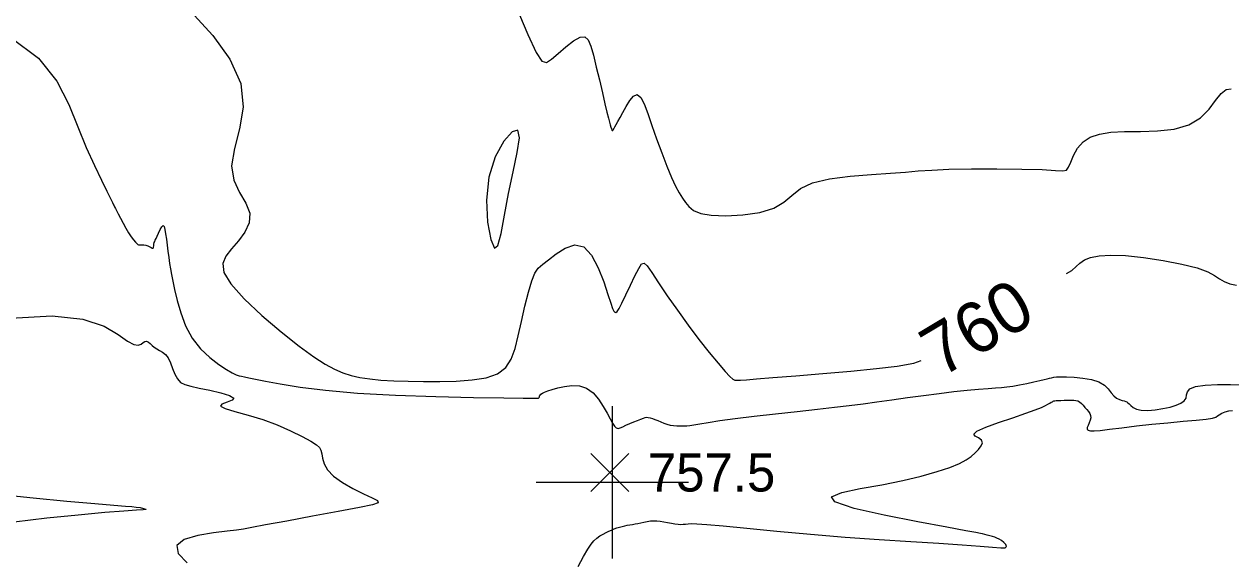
# Model space of a CAD drawing. Extents: x 2566142 to 2571431, y 418755 to 421584.
# Drawn here: x 2567768.3 to 2568243.6, y 420968.6 to 421180.6 of the extents above; entities that cross this region are included whole.
import ezdxf

# ---------------------------------------------------------------- set-up
doc = ezdxf.new("R2010")
doc.units = 0
for name, color, linetype in [('Contour_ADS_Label_Major', 7, 'Continuous'), ('Contour_ADS_Major', 7, 'Continuous'), ('Contour_ADS_Minor', 7, 'Continuous'), ('Contour_ADS_Spot_Elevation', 7, 'Continuous'), ('Contour_ADS_Tick', 7, 'Continuous')]:
    doc.layers.add(name, color=color, linetype=linetype)

# ---------------------------------------------------------------- blocks, each defined once
blk = doc.blocks.new('S890')
at = {"layer": 'Contour_ADS_Tick'}
for p, q in [((0, -0.5), (0, 0.5)), ((-0.5, 0), (0.5, 0))]:
    blk.add_line(p, q, dxfattribs=at)
blk = doc.blocks.new('S750')
at = {"layer": 'Contour_ADS_Spot_Elevation'}
for p, q in [((-0.5, 0.498), (0.5, -0.498)), ((-0.498, -0.5), (0.498, 0.5))]:
    blk.add_line(p, q, dxfattribs=at)

msp = doc.modelspace()

# ---------------------------------------------------------------- linework, layer by layer
at = {"layer": 'Contour_ADS_Major'}
for points in [[(2567835.26, 421184.06), (2567842.63, 421176.02), (2567849.28, 421166.75), (2567853.61, 421157.11), (2567854.55, 421147.85), (2567853.18, 421139.26), (2567851.12, 421131.49), (2567849.96, 421124.71), (2567850.86, 421119.02), (2567853.13, 421114.2), (2567855.61, 421109.97), (2567857.17, 421106.07), (2567856.94, 421102.28), (2567855.25, 421098.62), (2567852.75, 421095.17), (2567850.05, 421092.02), (2567847.79, 421089.16), (2567846.57, 421086.21), (2567847, 421082.7), (2567849.7, 421078.16), (2567854.97, 421072.33), (2567861.97, 421065.78), (2567869.6, 421059.29), (2567876.7, 421053.65), (2567882.42, 421049.44), (2567886.91, 421046.52), (2567890.59, 421044.54), (2567893.88, 421043.18), (2567897.13, 421042.13), (2567900.59, 421041.32), (2567904.42, 421040.71), (2567908.82, 421040.27), (2567913.89, 421039.97), (2567919.55, 421039.79), (2567925.65, 421039.72), (2567932.02, 421039.75), (2567938.49, 421039.89), (2567944.71, 421040.31), (2567950.27, 421041.21), (2567954.79, 421042.79), (2567958.01, 421045.22), (2567960.19, 421048.51), (2567961.7, 421052.67), (2567962.95, 421057.67), (2567964.24, 421063.41), (2567965.58, 421069.37), (2567966.93, 421074.9), (2567968.22, 421079.38), (2567969.46, 421082.4), (2567970.82, 421084.36), (2567972.55, 421085.9), (2567974.86, 421087.66), (2567977.91, 421090.01), (2567981.45, 421092.27), (2567985.16, 421093.51), (2567988.71, 421092.79), (2567991.83, 421089.54), (2567994.45, 421084.56), (2567996.57, 421079.01), (2567998.19, 421074.05), (2567999.33, 421070.6), (2568000.09, 421068.51), (2568000.59, 421067.44), (2568000.98, 421067), (2568001.36, 421066.93), (2568001.87, 421067.35), (2568002.63, 421068.52), (2568003.76, 421070.65), (2568005.32, 421073.86), (2568007.12, 421077.63), (2568008.9, 421081.33), (2568010.42, 421084.31), (2568011.53, 421086.04), (2568012.5, 421086.37)], [(2568012.5, 421086.37), (2568013.7, 421085.25), (2568015.51, 421082.66), (2568018.19, 421078.62), (2568021.63, 421073.51), (2568025.58, 421067.78), (2568029.82, 421061.9), (2568034.09, 421056.28), (2568038.14, 421051.2), (2568041.69, 421046.91), (2568044.47, 421043.68), (2568046.31, 421041.65), (2568047.46, 421040.6), (2568048.29, 421040.22), (2568049.15, 421040.2), (2568050.44, 421040.27), (2568052.77, 421040.43), (2568056.8, 421040.74), (2568063.16, 421041.24), (2568072.19, 421041.97), (2568082.89, 421042.86), (2568093.93, 421043.83), (2568104, 421044.79), (2568112.12, 421045.73), (2568118.71, 421046.99), (2568121.61, 421047.99)], [(2568178.81, 421082.22), (2568180.95, 421083.5), (2568182.69, 421084.99), (2568184.16, 421086.38), (2568185.89, 421087.6), (2568188.34, 421088.59), (2568191.75, 421089.26), (2568196.29, 421089.53), (2568202.12, 421089.31), (2568209.24, 421088.57), (2568216.92, 421087.41), (2568224.24, 421085.99), (2568230.31, 421084.46), (2568234.47, 421082.96), (2568237.15, 421081.54), (2568239.07, 421080.24), (2568240.9, 421079.11), (2568243.2, 421078.22), (2568245.83, 421077.73)]]:
    msp.add_lwpolyline(points, dxfattribs=at)
at = {"layer": 'Contour_ADS_Minor'}
for points in [[(2567961.95, 421187.66), (2567966.7, 421176.45), (2567970, 421169.36), (2567972.23, 421166), (2567974.02, 421165.42), (2567975.99, 421166.71), (2567978.61, 421168.98), (2567981.64, 421171.58), (2567984.67, 421173.92), (2567987.28, 421175.4), (2567989.19, 421175.56), (2567990.52, 421174.36), (2567991.56, 421171.9), (2567992.54, 421168.27), (2567993.66, 421163.65), (2567994.87, 421158.54), (2567996.05, 421153.5), (2567997.08, 421149.12), (2567997.86, 421145.84), (2567998.42, 421143.54), (2567998.83, 421141.95), (2567999.13, 421140.82), (2567999.38, 421139.94), (2567999.59, 421139.27), (2567999.77, 421138.83), (2567999.94, 421138.6), (2568000.11, 421138.62), (2568000.32, 421138.86), (2568000.59, 421139.33), (2568000.97, 421140.02), (2568001.49, 421140.95), (2568002.18, 421142.15), (2568003.05, 421143.73), (2568004.13, 421145.74), (2568005.42, 421148.15), (2568006.86, 421150.5), (2568008.35, 421152.23), (2568009.8, 421152.76), (2568011.16, 421151.67), (2568012.49, 421149.09), (2568013.92, 421145.32), (2568015.53, 421140.63), (2568017.41, 421135.34), (2568019.43, 421129.86), (2568021.44, 421124.64), (2568023.3, 421120.12), (2568024.9, 421116.64), (2568026.28, 421114.02), (2568027.55, 421111.99), (2568028.77, 421110.26), (2568030.12, 421108.63), (2568031.97, 421107.15), (2568034.77, 421105.97), (2568038.95, 421105.21), (2568044.74, 421104.98), (2568051.41, 421105.36), (2568058.02, 421106.37), (2568063.61, 421108.06), (2568067.57, 421110.39), (2568070.68, 421113.07), (2568074.04, 421115.74), (2568078.75, 421118.01), (2568085.55, 421119.62), (2568093.69, 421120.66), (2568102.07, 421121.32), (2568109.57, 421121.8), (2568115.44, 421122.26), (2568120.47, 421122.68), (2568125.78, 421123.05), (2568132.52, 421123.34), (2568141.42, 421123.5), (2568151.46, 421123.53), (2568161.21, 421123.44), (2568169.25, 421123.21), (2568174.5, 421122.89), (2568177.43, 421122.73), (2568178.87, 421123.05), (2568179.66, 421124.13), (2568180.5, 421126.17), (2568181.64, 421128.83), (2568183.22, 421131.65), (2568185.36, 421134.16), (2568188.19, 421136.01), (2568191.79, 421137.23), (2568196.26, 421137.92), (2568201.67, 421138.22), (2568208, 421138.3), (2568214.75, 421138.5), (2568221.31, 421139.22), (2568227.07, 421140.87), (2568231.57, 421143.66), (2568234.98, 421147.1)], [(2567763.01, 421175.34), (2567774, 421167.1), (2567781.22, 421158.12), (2567785.95, 421148.92), (2567789.47, 421140.03), (2567792.81, 421131.93), (2567795.98, 421124.86), (2567798.78, 421119.03), (2567800.95, 421114.66), (2567802.36, 421111.82), (2567803.14, 421110.21), (2567803.53, 421109.39), (2567803.73, 421108.96), (2567803.96, 421108.53), (2567804.28, 421107.94), (2567804.74, 421107.07), (2567805.39, 421105.82), (2567806.26, 421104.14), (2567807.28, 421102.17), (2567808.38, 421100.14), (2567809.47, 421098.27), (2567810.49, 421096.73), (2567811.4, 421095.54), (2567812.16, 421094.67), (2567812.73, 421094.08), (2567813.12, 421093.74), (2567813.41, 421093.58), (2567813.7, 421093.55), (2567814.12, 421093.56), (2567814.73, 421093.57), (2567815.49, 421093.53), (2567816.31, 421093.41), (2567817.09, 421093.18), (2567817.77, 421092.85), (2567818.32, 421092.5), (2567818.76, 421092.26), (2567819.07, 421092.27), (2567819.26, 421092.6), (2567819.38, 421093.15), (2567819.46, 421093.81), (2567819.57, 421094.44), (2567819.73, 421094.94), (2567819.96, 421095.43), (2567820.3, 421096.05), (2567820.73, 421096.96), (2567821.28, 421098.21), (2567821.89, 421099.56), (2567822.49, 421100.65), (2567823.02, 421101.14), (2567823.44, 421100.77), (2567823.77, 421099.64), (2567824.05, 421097.92), (2567824.33, 421095.81), (2567824.63, 421093.46), (2567824.95, 421091.02), (2567825.28, 421088.58), (2567825.61, 421086.28), (2567825.93, 421084.15), (2567826.32, 421081.93), (2567826.84, 421079.31), (2567827.56, 421075.94), (2567828.56, 421071.64), (2567829.97, 421066.72), (2567831.91, 421061.62), (2567834.5, 421056.79), (2567837.77, 421052.61), (2567841.4, 421049.14), (2567844.95, 421046.4), (2567848, 421044.4), (2567850.23, 421043.12), (2567851.79, 421042.38), (2567852.94, 421041.99), (2567853.94, 421041.78), (2567855.09, 421041.55), (2567856.77, 421041.21), (2567859.4, 421040.69), (2567863.4, 421039.89), (2567869.17, 421038.8), (2567876.97, 421037.52), (2567887.04, 421036.25), (2567899.62, 421035.14), (2567914.6, 421034.32), (2567930.44, 421033.78), (2567945.26, 421033.45), (2567957.19, 421033.26), (2567964.85, 421033.15), (2567968.9, 421033.11), (2567970.54, 421033.13), (2567970.93, 421033.19), (2567971.07, 421033.3), (2567971.17, 421033.44)], [(2568234.98, 421147.1), (2568237.59, 421150.52), (2568239.74, 421153.26), (2568241.71, 421154.76), (2568243.76, 421155.02)], [(2567762.91, 421064.63), (2567779.3, 421065.54), (2567791.48, 421064.27), (2567799.85, 421061.51), (2567805.36, 421058.28), (2567808.96, 421055.6), (2567811.47, 421054.26), (2567813.22, 421054.03), (2567814.41, 421054.46), (2567815.22, 421055.07), (2567815.83, 421055.48), (2567816.34, 421055.63), (2567816.82, 421055.53), (2567817.35, 421055.19), (2567817.97, 421054.64), (2567818.72, 421053.95), (2567819.58, 421053.22), (2567820.56, 421052.53), (2567821.66, 421051.95), (2567822.81, 421051.3), (2567823.94, 421050.39), (2567824.99, 421049.03), (2567825.91, 421047.1), (2567826.77, 421044.85), (2567827.65, 421042.6), (2567828.66, 421040.7), (2567829.91, 421039.38), (2567831.61, 421038.5), (2567833.97, 421037.83), (2567837.23, 421037.15), (2567841.41, 421036.28), (2567845.74, 421035.27), (2567849.25, 421034.21), (2567850.97, 421033.21), (2567850.31, 421032.34), (2567848.27, 421031.55), (2567846.24, 421030.79), (2567845.63, 421029.97), (2567847.45, 421029.04), (2567851.33, 421027.91), (2567856.54, 421026.51), (2567862.32, 421024.75), (2567868.02, 421022.62), (2567873.27, 421020.31), (2567877.77, 421018.08), (2567881.22, 421016.17), (2567883.44, 421014.76), (2567884.66, 421013.66), (2567885.23, 421012.59), (2567885.5, 421011.27), (2567885.81, 421009.49), (2567886.49, 421007.32)], [(2567971.17, 421033.44), (2567971.23, 421033.62), (2567971.28, 421033.83), (2567971.35, 421034.09), (2567971.51, 421034.38), (2567971.83, 421034.71), (2567972.41, 421035.1), (2567973.31, 421035.54), (2567974.59, 421036.03), (2567976.29, 421036.57), (2567978.45, 421037.17), (2567981.08, 421037.77), (2567984.01, 421038.15), (2567987.01, 421038.03), (2567989.86, 421037.12), (2567992.39, 421035.25), (2567994.56, 421032.72), (2567996.39, 421029.92), (2567997.88, 421027.23), (2567999.06, 421025), (2568000, 421023.29), (2568000.79, 421022.09), (2568001.52, 421021.4), (2568002.27, 421021.2), (2568003.12, 421021.4), (2568004.12, 421021.87), (2568005.34, 421022.49), (2568006.81, 421023.15), (2568008.39, 421023.8), (2568009.91, 421024.39), (2568011.22, 421024.9), (2568012.19, 421025.27), (2568012.9, 421025.51), (2568013.5, 421025.61), (2568014.12, 421025.57), (2568014.88, 421025.4), (2568015.77, 421025.11), (2568016.78, 421024.73), (2568017.87, 421024.29), (2568019.02, 421023.8), (2568020.23, 421023.33), (2568021.49, 421022.9), (2568022.78, 421022.57), (2568024.1, 421022.37), (2568025.38, 421022.27), (2568026.57, 421022.24), (2568027.6, 421022.24), (2568028.46, 421022.24), (2568029.33, 421022.28), (2568030.46, 421022.39), (2568032.09, 421022.64), (2568034.45, 421023.04), (2568037.78, 421023.59), (2568042.31, 421024.29), (2568048.3, 421025.1), (2568055.81, 421026.01), (2568064.23, 421026.96), (2568072.79, 421027.91), (2568080.73, 421028.78), (2568087.48, 421029.55), (2568093.32, 421030.25), (2568098.73, 421030.94), (2568104.2, 421031.68), (2568110.09, 421032.51), (2568116.28, 421033.39), (2568122.56, 421034.25), (2568128.68, 421035.04), (2568134.44, 421035.72), (2568139.68, 421036.27), (2568144.25, 421036.69), (2568148.02, 421037.01), (2568150.93, 421037.23), (2568153.26, 421037.4), (2568155.39, 421037.61), (2568157.67, 421037.93), (2568160.36, 421038.39), (2568163.26, 421038.96), (2568166.05, 421039.54), (2568168.41, 421040.07), (2568170.11, 421040.49), (2568171.29, 421040.8), (2568172.16, 421041.04), (2568172.92, 421041.22), (2568173.8, 421041.38), (2568174.97, 421041.49), (2568176.62, 421041.54), (2568178.91, 421041.51), (2568181.91, 421041.37), (2568185.32, 421041.04), (2568188.7, 421040.46), (2568191.62, 421039.54), (2568193.79, 421038.25), (2568195.33, 421036.77), (2568196.49, 421035.29), (2568197.52, 421034.03), (2568198.6, 421033.14), (2568199.7, 421032.58), (2568200.72, 421032.25), (2568201.57, 421032.04), (2568202.19, 421031.86), (2568202.66, 421031.65)], [(2568202.66, 421031.65), (2568203.07, 421031.33), (2568203.53, 421030.86), (2568204.16, 421030.2), (2568205.07, 421029.48), (2568206.42, 421028.83), (2568208.32, 421028.42), (2568210.85, 421028.35), (2568213.78, 421028.58), (2568216.8, 421029.04), (2568219.63, 421029.66), (2568222.01, 421030.37), (2568223.87, 421031.18), (2568225.18, 421032.12), (2568225.92, 421033.2), (2568226.17, 421034.42), (2568226.45, 421035.68), (2568227.38, 421036.84), (2568229.6, 421037.75), (2568233.48, 421038.32), (2568238.38, 421038.56), (2568243.44, 421038.55), (2568247.77, 421038.35)], [(2568155, 420975.41), (2568154.21, 420976.25), (2568153.23, 420977.02), (2568152.31, 420977.6), (2568151.45, 420978.02), (2568150.6, 420978.34), (2568149.69, 420978.61), (2568148.68, 420978.89), (2568147.63, 420979.17), (2568146.65, 420979.43), (2568145.82, 420979.64), (2568145.01, 420979.83), (2568143.2, 420980.18), (2568139.18, 420980.92), (2568131.7, 420982.27), (2568120.25, 420984.37), (2568107.09, 420986.97), (2568095.2, 420989.7), (2568087.56, 420992.24), (2568086.33, 420994.31), (2568090.34, 420996.02), (2568097.62, 420997.53), (2568106.18, 420999.05), (2568114.34, 421000.71), (2568121.63, 421002.45), (2568127.88, 421004.21), (2568132.92, 421005.88), (2568136.66, 421007.4), (2568139.34, 421008.81), (2568141.29, 421010.17), (2568142.84, 421011.54), (2568144.22, 421012.94), (2568145.28, 421014.32), (2568145.77, 421015.58), (2568145.44, 421016.64), (2568144.24, 421017.45), (2568142.9, 421018.17), (2568142.36, 421018.99), (2568143.53, 421020.13), (2568147.02, 421021.7), (2568152.1, 421023.56), (2568157.7, 421025.46), (2568162.78, 421027.18), (2568166.5, 421028.52), (2568168.97, 421029.53), (2568170.54, 421030.26), (2568171.55, 421030.8), (2568172.3, 421031.2), (2568172.88, 421031.51), (2568173.31, 421031.74), (2568173.64, 421031.91), (2568173.91, 421032.04), (2568174.24, 421032.13), (2568174.72, 421032.2), (2568175.48, 421032.25), (2568176.58, 421032.28), (2568177.91, 421032.31), (2568179.31, 421032.33), (2568180.6, 421032.33), (2568181.68, 421032.33), (2568182.56, 421032.25), (2568183.32, 421032.06), (2568184.02, 421031.68), (2568184.73, 421031.09), (2568185.44, 421030.33), (2568186.14, 421029.5), (2568186.82, 421028.67), (2568187.46, 421027.9), (2568188, 421027.15), (2568188.35, 421026.35), (2568188.44, 421025.46), (2568188.23, 421024.43), (2568187.83, 421023.36), (2568187.38, 421022.36), (2568187.05, 421021.56), (2568186.94, 421021.04), (2568187.02, 421020.75), (2568187.22, 421020.6), (2568187.45, 421020.49), (2568187.74, 421020.36), (2568188.36, 421020.26), (2568189.69, 421020.27), (2568192.1, 421020.46), (2568195.85, 421020.89), (2568200.71, 421021.5), (2568206.38, 421022.2), (2568212.52, 421022.88), (2568218.8, 421023.49), (2568224.76, 421024.02), (2568229.95, 421024.49), (2568233.91, 421024.91), (2568236.33, 421025.3), (2568237.61, 421025.69), (2568238.3, 421026.12), (2568238.94, 421026.63), (2568239.98, 421027.22), (2568241.34, 421027.79), (2568242.83, 421028.2), (2568244.26, 421028.34)], [(2567886.49, 421007.32), (2567887.84, 421004.9), (2567890.18, 421002.37), (2567893.67, 420999.86), (2567897.8, 420997.52), (2567901.93, 420995.47), (2567905.37, 420993.87), (2567907.5, 420992.76), (2567907.74, 420991.95), (2567905.54, 420991.13), (2567900.35, 420990.02), (2567892.02, 420988.44), (2567881.9, 420986.58), (2567871.78, 420984.73), (2567863.4, 420983.19), (2567858, 420982.18), (2567854.65, 420981.57), (2567851.91, 420981.15), (2567848.3, 420980.72), (2567842.89, 420980.08), (2567836.72, 420979.03), (2567831.37, 420977.42), (2567828.39, 420975.06), (2567828.95, 420971.87), (2567832.57, 420968.2)], [(2567758.01, 420995.33), (2567771.83, 420993.89), (2567785.15, 420992.59), (2567796.21, 420991.57), (2567803.7, 420990.92), (2567808.21, 420990.58), (2567810.76, 420990.39), (2567812.41, 420990.23), (2567813.98, 420990), (2567815.36, 420989.72), (2567816.25, 420989.45), (2567816.33, 420989.24), (2567815.24, 420989.11), (2567812.51, 420988.97), (2567807.61, 420988.67), (2567800.04, 420988.08), (2567789.57, 420987.1), (2567777.23, 420985.8), (2567764.35, 420984.29)], [(2567986.48, 420966.74), (2567988.68, 420970.74), (2567990.3, 420973.58), (2567991.58, 420975.55), (2567992.72, 420976.95), (2567993.89, 420978.03), (2567995.11, 420978.89), (2567996.33, 420979.58), (2567997.5, 420980.17), (2567998.61, 420980.7), (2567999.66, 420981.18), (2568000.68, 420981.61), (2568001.7, 420981.99), (2568002.74, 420982.33), (2568003.8, 420982.62), (2568004.85, 420982.86), (2568005.88, 420983.07), (2568006.89, 420983.23), (2568007.89, 420983.39), (2568008.93, 420983.56), (2568010.02, 420983.77), (2568011.2, 420984.03), (2568012.44, 420984.31), (2568013.71, 420984.56), (2568015, 420984.74), (2568016.27, 420984.8), (2568017.56, 420984.75), (2568018.88, 420984.61), (2568020.27, 420984.39), (2568021.74, 420984.13), (2568023.23, 420983.85), (2568024.65, 420983.61), (2568025.92, 420983.46), (2568026.99, 420983.41), (2568027.93, 420983.46), (2568028.84, 420983.55), (2568029.81, 420983.65), (2568031.06, 420983.7), (2568033.25, 420983.63), (2568037.16, 420983.36), (2568043.58, 420982.79), (2568053, 420981.89), (2568064.77, 420980.77), (2568077.98, 420979.56), (2568091.69, 420978.43), (2568105.05, 420977.47), (2568117.51, 420976.69), (2568128.59, 420976.01), (2568137.81, 420975.4), (2568144.81, 420974.82), (2568149.76, 420974.36), (2568152.96, 420974.12), (2568154.7, 420974.2), (2568155.27, 420974.67), (2568155, 420975.41)]]:
    msp.add_lwpolyline(points, dxfattribs=at)
msp.add_lwpolyline([(2567951.37, 421120.24), (2567950.46, 421111.19), (2567950.87, 421102.49), (2567952.07, 421095.67), (2567953.55, 421092.25), (2567954.91, 421093.3), (2567956.19, 421098.06), (2567957.54, 421105.3), (2567959.11, 421113.79), (2567960.94, 421122.37), (2567962.55, 421130.02), (2567963.37, 421135.8), (2567962.81, 421138.74), (2567960.53, 421138.17), (2567957.23, 421134.46), (2567953.86, 421128.26), (2567951.37, 421120.24)], close=True, dxfattribs=at)

# ---------------------------------------------------------------- block references
at = {"layer": 'Contour_ADS_Spot_Elevation', "xscale": 15, "yscale": 15}
msp.add_blockref('S750', (2567998.96, 421003.86), dxfattribs=at)
at = {"layer": 'Contour_ADS_Tick', "xscale": 60, "yscale": 60}
msp.add_blockref('S890', (2568000, 421000), dxfattribs=at)

# ---------------------------------------------------------------- texts
at = {"layer": 'Contour_ADS_Label_Major'}
msp.add_text('760', height=20, rotation=30.8963, dxfattribs=at).set_placement((2568129.44, 421041.02))
at = {"layer": 'Contour_ADS_Spot_Elevation'}
msp.add_text('757.5', height=15, dxfattribs=at).set_placement((2568013.96, 420996.36))

doc.saveas('drawing.dxf')
